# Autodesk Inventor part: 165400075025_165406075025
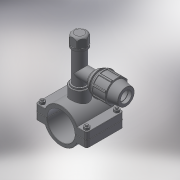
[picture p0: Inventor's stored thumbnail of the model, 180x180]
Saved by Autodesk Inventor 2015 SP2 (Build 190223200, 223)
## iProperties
Created: 2017-05
Part Number: 165400075025_165406075025
Material: Generic
Description: PLASSON TAPPER FOR PE+PVC PIPE 75-25
Document SubType Name: Modeling
Designer: KIM
Density: 1 g/cm^3
Appearance: Default
Author: KIM
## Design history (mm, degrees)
derived "16540.ipt"
feature "Solid1::16540.ipt"
feature "Solid2::16540.ipt"
tag "TaggingFeature1"
body "Solid1"
other parameters: "d0" = 93.75, "d1" = 122, "d2" = 37.5, "d3" = 75, "d4" = 98, "d5" = 0, "d6" = 6.1, "d7" = 122, "d8" = 0.1, "d10" = 0, "d11" = 0.75, "d14" = 39.3783, "d20" = 0.75, "d23" = 0.75, "d37" = 8, "d38" = 45.5, "d39" = 0, "d40" = 3, "d41" = 5, "d42" = 0, "d43" = 6, "d44" = 3, "d45" = 0, "d46" = 0.75, "d51" = 67, "d52" = 30.291, "d53" = 21, "d54" = 0, "d55" = 25, "d57" = 0, "d58" = 81, "d60" = 0, "d63" = 8, "d66" = 82, "d67" = 25, "d68" = 8.75, "d69" = 21, "d70" = 54, "d71" = 40.5, "d72" = 1.5, "d73" = 43.2, "d74" = 120 deg, "d75" = 37.5, "d76" = 10 deg, "d77" = 48.6, "d78" = 31.5, "d79" = 61, "d81" = 105, "d82" = 6.1, "d87" = 15, "d90" = 50.22, "d91" = 35 deg, "d92" = 17.5 deg, "d94" = 0, "d96" = 360 deg, "d98" = 0.5, "d99" = 67.1, "d100" = 27.2619, "d101" = 135 deg, "d102" = 1.08, "d105" = 2.7, "d106" = 0, "d107" = 0.1, "d108" = 27.2619, "d109" = 33.3201, "d111" = 26, "d112" = 6.5, "d113" = 3.5, "d116" = 0, "d118" = 21, "d119" = 0, "d122" = 57, "d_" = 75, "B_" = 25, "G_" = 30.291, "A_" = 67, "L_" = 122, "L_1" = 98, "l_2" = 21, "d_1" = 25, "E_" = 54, "l_" = 61, "H_" = 105, "H_1" = 57
